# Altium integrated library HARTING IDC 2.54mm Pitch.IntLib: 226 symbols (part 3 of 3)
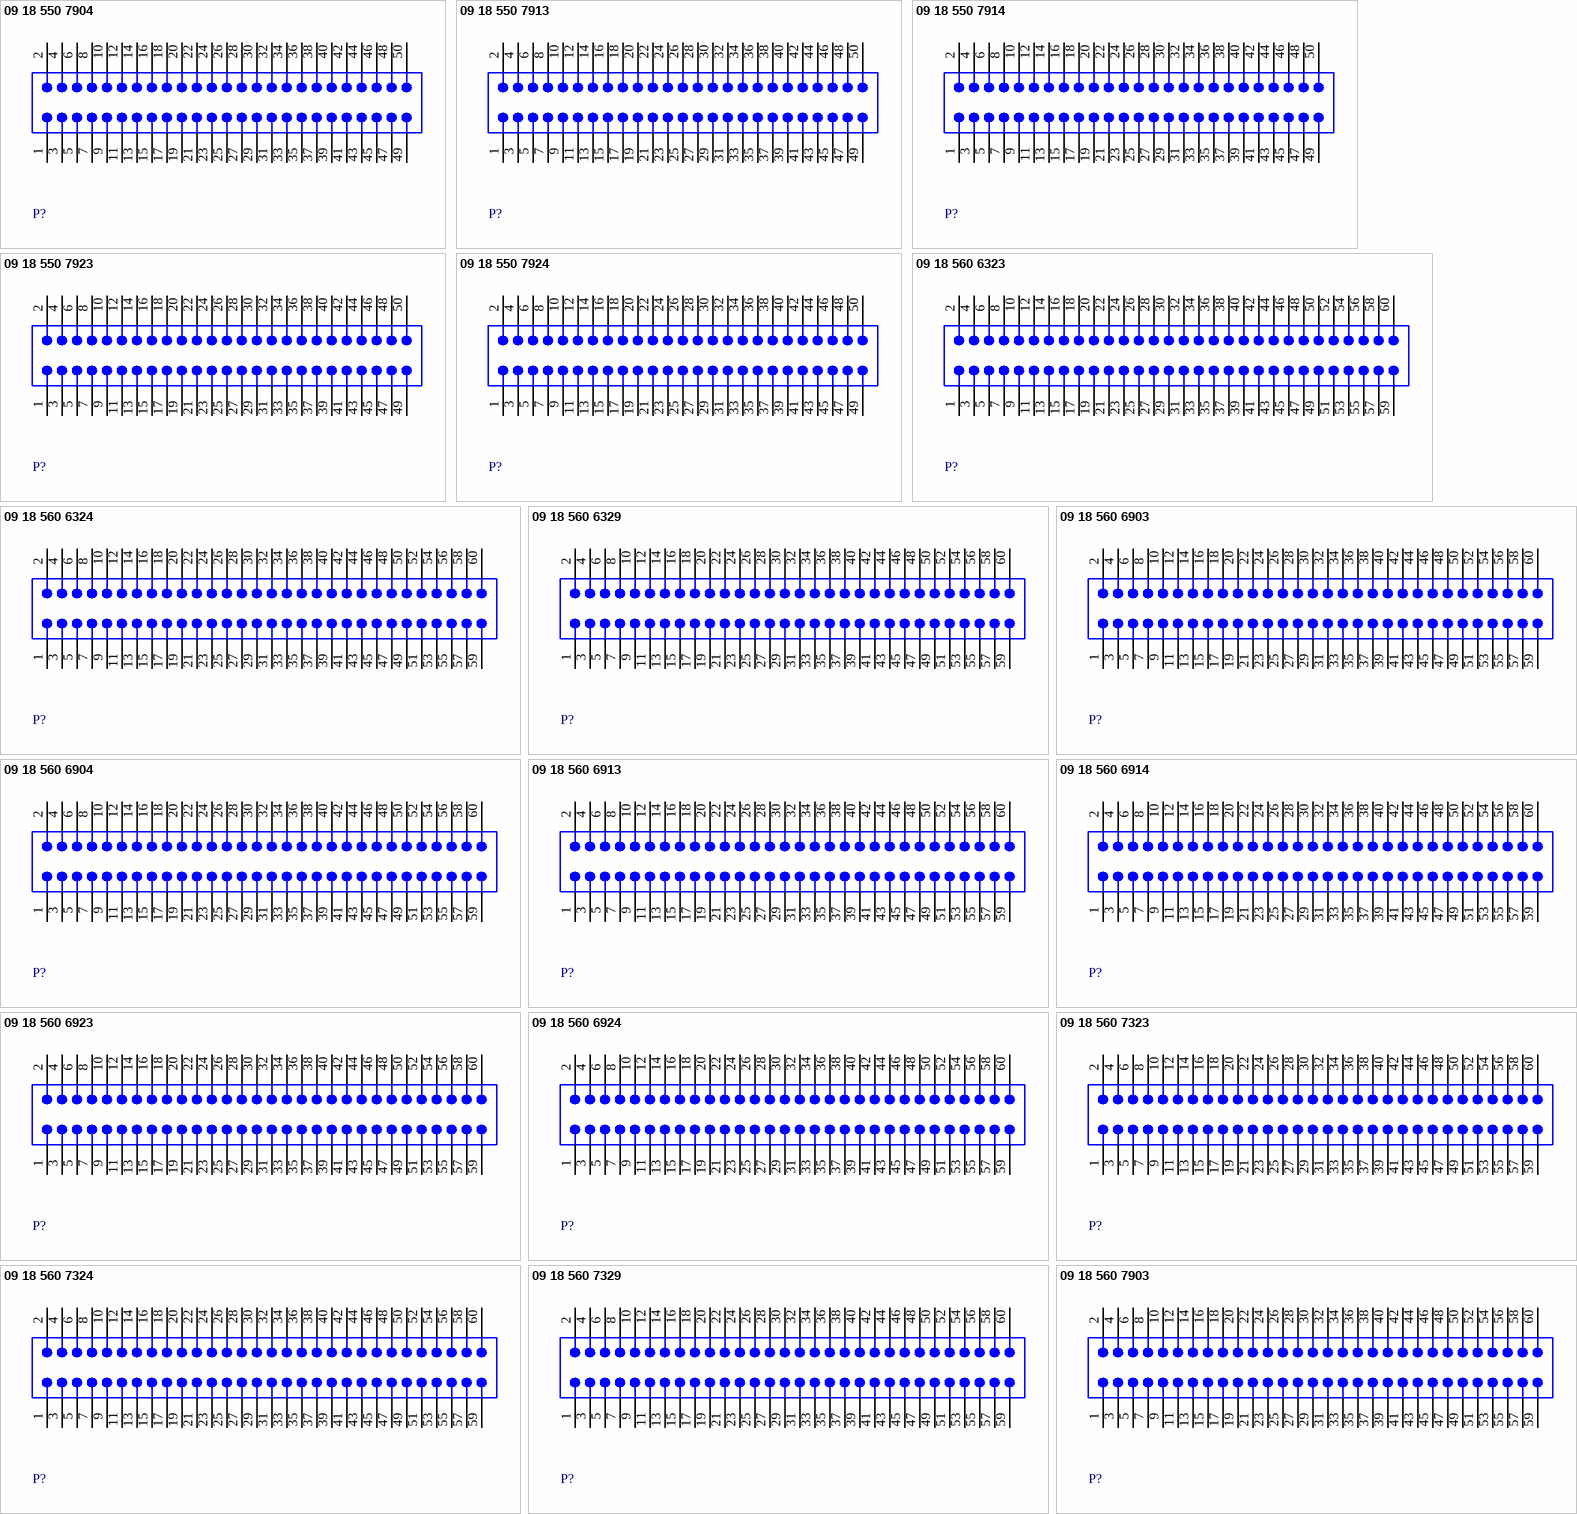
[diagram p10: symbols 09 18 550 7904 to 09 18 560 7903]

## 09 18 560 7324
designator P?
Flat Cable Connector (IDC), Low-Profile Male Header, Straight Solder Pin, 60 Contacts, Performance Level 3; PCB_Layout: Complies with manufacturer's recommendation.; DrillSize: Corresponds to nominal value.
footprint 918560x324 (Connector; IDC, Low Profile Male Header, Thru-Hole; 60 Position; Vertical; Pitch 2.54 mm; Body 84.02 x 9.2 x 9.45 mm (LxWxH))
pins: 1, 2, 3, 4, 5, 6, 7, 8, 9, 10, 11, 12, 13, 14, 15, 16, 17, 18, 19, 20, 21, 22, 23, 24, 25, 26, 27, 28, 29, 30, 31, 32, 33, 34, 35, 36, 37, 38, 39, 40, 41, 42, 43, 44, 45, 46, 47, 48, 49, 50, 51, 52, 53, 54, 55, 56, 57, 58, 59, 60

## 09 18 560 7329
designator P?
Flat Cable Connector (IDC), Standard Male Header, Straight Press-in Pin, 60 Contacts, Performance Level 3; PCB_Layout: Complies with manufacturer's recommendation.; DrillSize: Corresponds to nominal value.
footprint 918560x329 (Connector; IDC, Straight Press-in Pin, Thru-Hole; 60 Position; Vertical; Pitch 2.54 mm; Body 84.02 x 9.2 x 9.45 mm (LxWxH))
pins: 1, 2, 3, 4, 5, 6, 7, 8, 9, 10, 11, 12, 13, 14, 15, 16, 17, 18, 19, 20, 21, 22, 23, 24, 25, 26, 27, 28, 29, 30, 31, 32, 33, 34, 35, 36, 37, 38, 39, 40, 41, 42, 43, 44, 45, 46, 47, 48, 49, 50, 51, 52, 53, 54, 55, 56, 57, 58, 59, 60

## 09 18 560 7903
designator P?
Flat Cable Connector (IDC), Standard Male Header, Angled Solder Pin, 60 Contacts, Long Levers, Performance Level 3; PCB_Layout: Complies with manufacturer's recommendation.; DrillSize: Corresponds to nominal value.
footprint 918560x903 (Connector; IDC, Thru-Hole; 60 Position; Right Angle; Pitch 2.54 mm; Body 95.80 x 8.5 x 25.75 mm (LxHxW), Locking levers)
pins: 1, 2, 3, 4, 5, 6, 7, 8, 9, 10, 11, 12, 13, 14, 15, 16, 17, 18, 19, 20, 21, 22, 23, 24, 25, 26, 27, 28, 29, 30, 31, 32, 33, 34, 35, 36, 37, 38, 39, 40, 41, 42, 43, 44, 45, 46, 47, 48, 49, 50, 51, 52, 53, 54, 55, 56, 57, 58, 59, 60

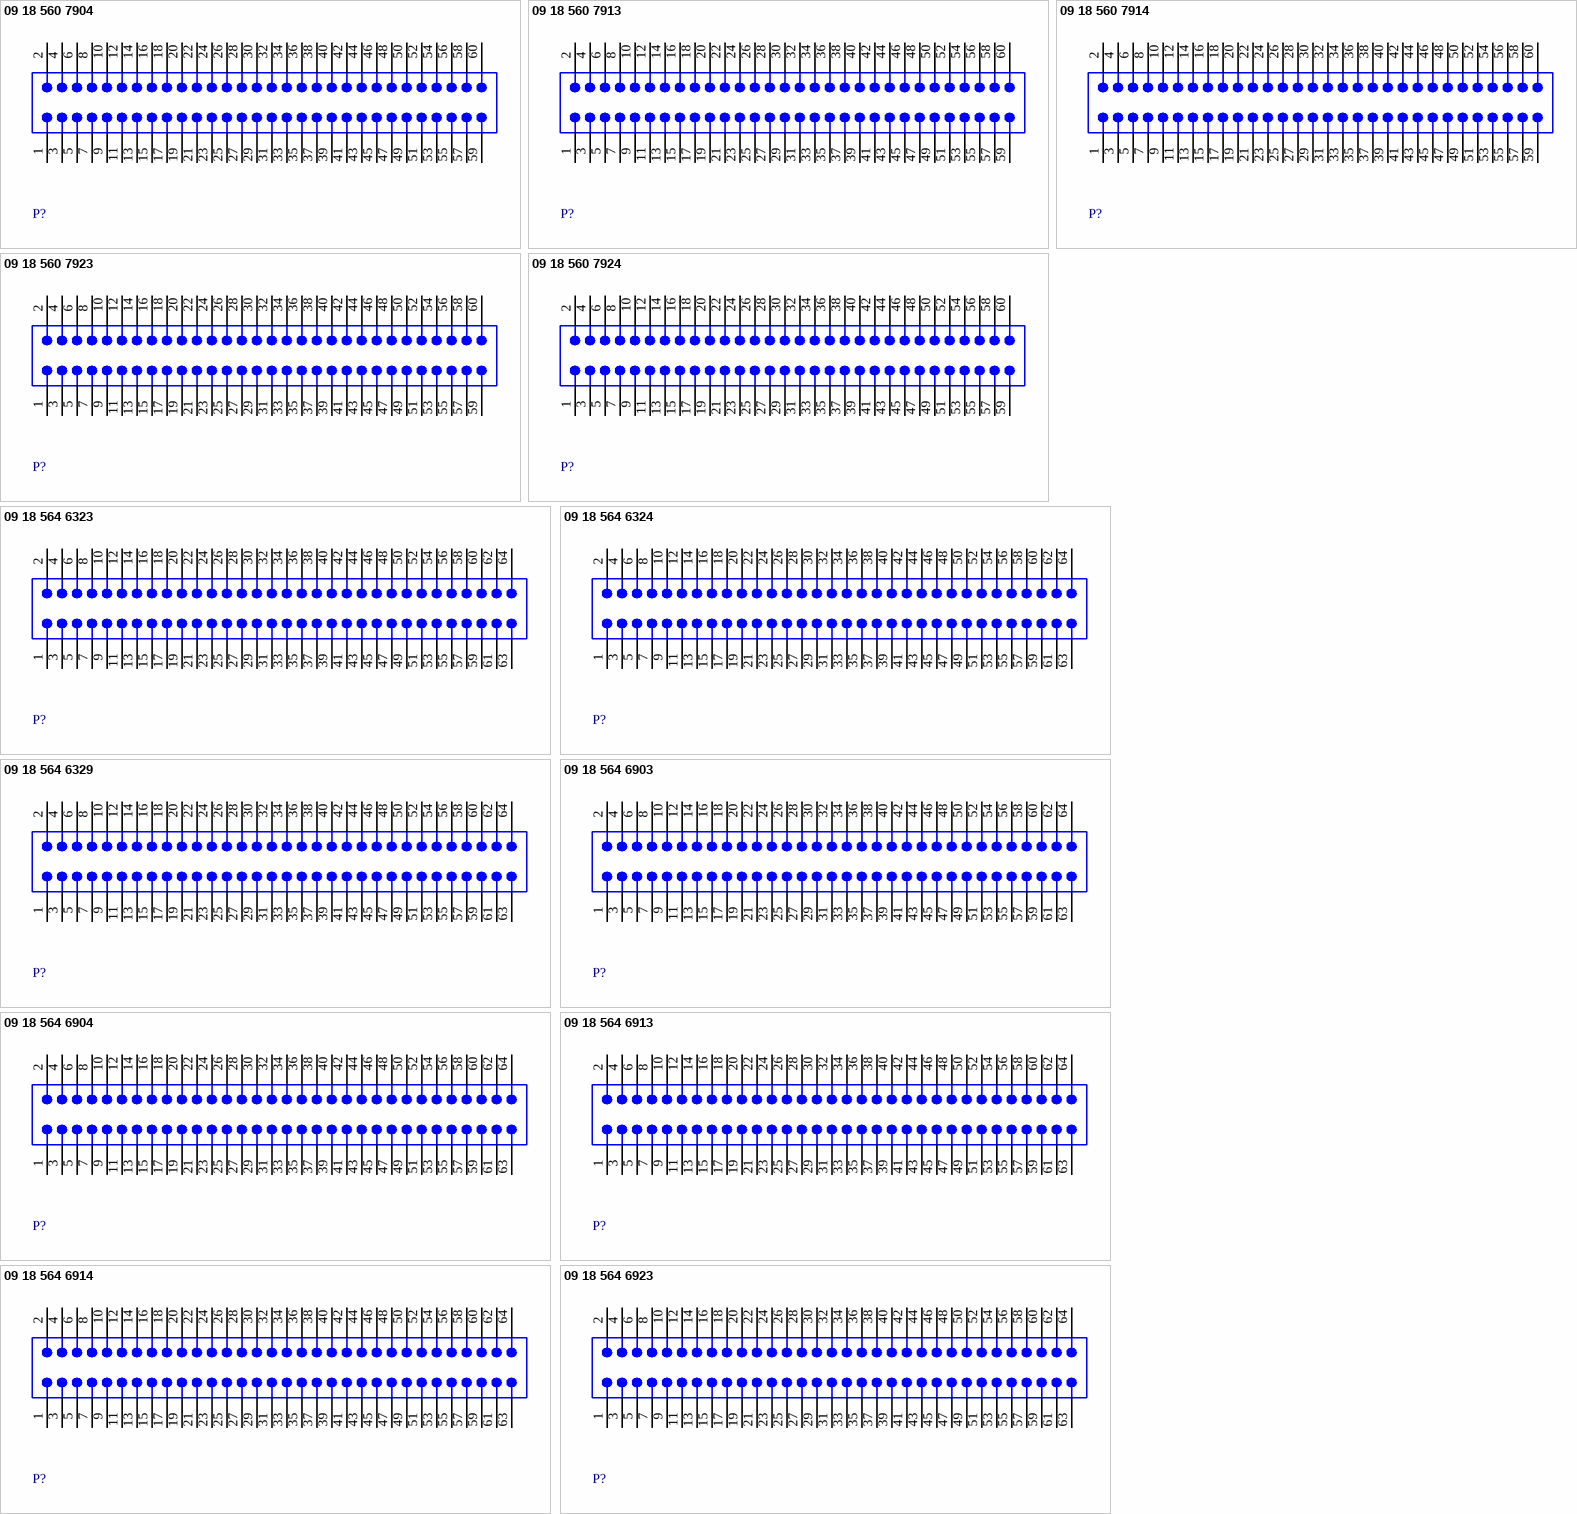
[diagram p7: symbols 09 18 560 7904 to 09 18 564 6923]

## 09 18 560 7904
designator P?
Flat Cable Connector (IDC), Standard Male Header, Straight Solder Pin, 60 Contacts, Long Levers, Performance Level 3; PCB_Layout: Complies with manufacturer's recommendation.; DrillSize: Corresponds to nominal value.
footprint 918560x904 (Connector; IDC, Thru-Hole; 60 Position; Vertical; Pitch 2.54 mm; Body 95.80 x 8.5 x 25.75 mm (LxWxH), Locking levers)
pins: 1, 2, 3, 4, 5, 6, 7, 8, 9, 10, 11, 12, 13, 14, 15, 16, 17, 18, 19, 20, 21, 22, 23, 24, 25, 26, 27, 28, 29, 30, 31, 32, 33, 34, 35, 36, 37, 38, 39, 40, 41, 42, 43, 44, 45, 46, 47, 48, 49, 50, 51, 52, 53, 54, 55, 56, 57, 58, 59, 60

## 09 18 560 7913
designator P?
Flat Cable Connector (IDC), Standard Male Header, Angled Solder Pin, 60 Contacts, Short Levers, Performance Level 3; PCB_Layout: Complies with manufacturer's recommendation.; DrillSize: Corresponds to nominal value.
footprint 918560x913 (Connector; IDC, Thru-Hole; 60 Position; Right Angle; Pitch 2.54 mm; Body 95.80 x 8.5 x 23.30 mm (LxHxW), Locking levers)
pins: 1, 2, 3, 4, 5, 6, 7, 8, 9, 10, 11, 12, 13, 14, 15, 16, 17, 18, 19, 20, 21, 22, 23, 24, 25, 26, 27, 28, 29, 30, 31, 32, 33, 34, 35, 36, 37, 38, 39, 40, 41, 42, 43, 44, 45, 46, 47, 48, 49, 50, 51, 52, 53, 54, 55, 56, 57, 58, 59, 60

## 09 18 560 7914
designator P?
Flat Cable Connector (IDC), Standard Male Header, Straight Solder Pin, 60 Contacts, Short Levers, Performance Level 3; PCB_Layout: Complies with manufacturer's recommendation.; DrillSize: Corresponds to nominal value.
footprint 918560x914 (Connector; IDC, Thru-Hole; 60 Position; Vertical; Pitch 2.54 mm; Body 95.80 x 8.5 x 23.30 mm (LxWxH), Locking levers)
pins: 1, 2, 3, 4, 5, 6, 7, 8, 9, 10, 11, 12, 13, 14, 15, 16, 17, 18, 19, 20, 21, 22, 23, 24, 25, 26, 27, 28, 29, 30, 31, 32, 33, 34, 35, 36, 37, 38, 39, 40, 41, 42, 43, 44, 45, 46, 47, 48, 49, 50, 51, 52, 53, 54, 55, 56, 57, 58, 59, 60

## 09 18 560 7923
designator P?
Flat Cable Connector (IDC), Standard Male Header, Angled Solder Pin, 60 Contacts, Without Levers, Performance Level 3; PCB_Layout: Complies with manufacturer's recommendation.; DrillSize: Corresponds to nominal value.
footprint 918560x923 (Connector; IDC, Thru-Hole; 60 Position; Right Angle; Pitch 2.54 mm; Body 95.80 x 8.5 x 17.30 mm (LxHxW), Without locking levers)
pins: 1, 2, 3, 4, 5, 6, 7, 8, 9, 10, 11, 12, 13, 14, 15, 16, 17, 18, 19, 20, 21, 22, 23, 24, 25, 26, 27, 28, 29, 30, 31, 32, 33, 34, 35, 36, 37, 38, 39, 40, 41, 42, 43, 44, 45, 46, 47, 48, 49, 50, 51, 52, 53, 54, 55, 56, 57, 58, 59, 60

## 09 18 560 7924
designator P?
Flat Cable Connector (IDC), Standard Male Header, Straight Solder Pin, 60 Contacts, Without Levers, Performance Level 3; PCB_Layout: Complies with manufacturer's recommendation.; DrillSize: Corresponds to nominal value.
footprint 918560x924 (Connector; IDC, Thru-Hole; 60 Position; Vertical; Pitch 2.54 mm; Body 95.80 x 8.5 x 17.30 mm (LxWxH), Without locking levers)
pins: 1, 2, 3, 4, 5, 6, 7, 8, 9, 10, 11, 12, 13, 14, 15, 16, 17, 18, 19, 20, 21, 22, 23, 24, 25, 26, 27, 28, 29, 30, 31, 32, 33, 34, 35, 36, 37, 38, 39, 40, 41, 42, 43, 44, 45, 46, 47, 48, 49, 50, 51, 52, 53, 54, 55, 56, 57, 58, 59, 60

## 09 18 564 6323
designator P?
Flat Cable Connector (IDC), Low-Profile Male Header, Angled Solder Pin, 64 Contacts, Performance Level 2; PCB_Layout: Complies with manufacturer's recommendation.; DrillSize: Corresponds to nominal value.
footprint 918564x323 (Connector; IDC, Low Profile Male Header, Thru-Hole; 64 Position; Right Angle; Pitch 2.54 mm; Body 89.10 x 8.9 x 9.2 mm (LxWxH))
pins: 1, 2, 3, 4, 5, 6, 7, 8, 9, 10, 11, 12, 13, 14, 15, 16, 17, 18, 19, 20, 21, 22, 23, 24, 25, 26, 27, 28, 29, 30, 31, 32, 33, 34, 35, 36, 37, 38, 39, 40, 41, 42, 43, 44, 45, 46, 47, 48, 49, 50, 51, 52, 53, 54, 55, 56, 57, 58, 59, 60, 61, 62, 63, 64

## 09 18 564 6324
designator P?
Flat Cable Connector (IDC), Low-Profile Male Header, Straight Solder Pin, 64 Contacts, Performance Level 2; PCB_Layout: Complies with manufacturer's recommendation.; DrillSize: Corresponds to nominal value.
footprint 918564x324 (Connector; IDC, Low Profile Male Header, Thru-Hole; 64 Position; Vertical; Pitch 2.54 mm; Body 89.10 x 9.2 x 9.45 mm (LxWxH))
pins: 1, 2, 3, 4, 5, 6, 7, 8, 9, 10, 11, 12, 13, 14, 15, 16, 17, 18, 19, 20, 21, 22, 23, 24, 25, 26, 27, 28, 29, 30, 31, 32, 33, 34, 35, 36, 37, 38, 39, 40, 41, 42, 43, 44, 45, 46, 47, 48, 49, 50, 51, 52, 53, 54, 55, 56, 57, 58, 59, 60, 61, 62, 63, 64

## 09 18 564 6329
designator P?
Flat Cable Connector (IDC), Standard Male Header, Straight Press-in Pin, 64 Contacts, Performance Level 2; PCB_Layout: Complies with manufacturer's recommendation.; DrillSize: Corresponds to nominal value.
footprint 918564x329 (Connector; IDC, Straight Press-in Pin, Thru-Hole; 64 Position; Vertical; Pitch 2.54 mm; Body 89.10 x 9.2 x 9.45 mm (LxWxH))
pins: 1, 2, 3, 4, 5, 6, 7, 8, 9, 10, 11, 12, 13, 14, 15, 16, 17, 18, 19, 20, 21, 22, 23, 24, 25, 26, 27, 28, 29, 30, 31, 32, 33, 34, 35, 36, 37, 38, 39, 40, 41, 42, 43, 44, 45, 46, 47, 48, 49, 50, 51, 52, 53, 54, 55, 56, 57, 58, 59, 60, 61, 62, 63, 64

## 09 18 564 6903
designator P?
Flat Cable Connector (IDC), Standard Male Header, Angled Solder Pin, 64 Contacts, Long Levers, Performance Level 2; PCB_Layout: Complies with manufacturer's recommendation.; DrillSize: Corresponds to nominal value.
footprint 918564x903 (Connector; IDC, Thru-Hole; 64 Position; Right Angle; Pitch 2.54 mm; Body 100.88 x 8.5 x 25.75 mm (LxHxW), Locking levers)
pins: 1, 2, 3, 4, 5, 6, 7, 8, 9, 10, 11, 12, 13, 14, 15, 16, 17, 18, 19, 20, 21, 22, 23, 24, 25, 26, 27, 28, 29, 30, 31, 32, 33, 34, 35, 36, 37, 38, 39, 40, 41, 42, 43, 44, 45, 46, 47, 48, 49, 50, 51, 52, 53, 54, 55, 56, 57, 58, 59, 60, 61, 62, 63, 64

## 09 18 564 6904
designator P?
Flat Cable Connector (IDC), Standard Male Header, Straight Solder Pin, 64 Contacts, Long Levers, Performance Level 2; PCB_Layout: Complies with manufacturer's recommendation.; DrillSize: Corresponds to nominal value.
footprint 918564x904 (Connector; IDC, Thru-Hole; 64 Position; Vertical; Pitch 2.54 mm; Body 100.88 x 8.5 x 25.75 mm (LxWxH), Locking levers)
pins: 1, 2, 3, 4, 5, 6, 7, 8, 9, 10, 11, 12, 13, 14, 15, 16, 17, 18, 19, 20, 21, 22, 23, 24, 25, 26, 27, 28, 29, 30, 31, 32, 33, 34, 35, 36, 37, 38, 39, 40, 41, 42, 43, 44, 45, 46, 47, 48, 49, 50, 51, 52, 53, 54, 55, 56, 57, 58, 59, 60, 61, 62, 63, 64

## 09 18 564 6913
designator P?
Flat Cable Connector (IDC), Standard Male Header, Angled Solder Pin, 64 Contacts, Short Levers, Performance Level 2; PCB_Layout: Complies with manufacturer's recommendation.; DrillSize: Corresponds to nominal value.
footprint 918564x913 (Connector; IDC, Thru-Hole; 64 Position; Right Angle; Pitch 2.54 mm; Body 100.88 x 8.5 x 23.30 mm (LxHxW), Locking levers)
pins: 1, 2, 3, 4, 5, 6, 7, 8, 9, 10, 11, 12, 13, 14, 15, 16, 17, 18, 19, 20, 21, 22, 23, 24, 25, 26, 27, 28, 29, 30, 31, 32, 33, 34, 35, 36, 37, 38, 39, 40, 41, 42, 43, 44, 45, 46, 47, 48, 49, 50, 51, 52, 53, 54, 55, 56, 57, 58, 59, 60, 61, 62, 63, 64

## 09 18 564 6914
designator P?
Flat Cable Connector (IDC), Standard Male Header, Straight Solder Pin, 64 Contacts, Short Levers, Performance Level 2; PCB_Layout: Complies with manufacturer's recommendation.; DrillSize: Corresponds to nominal value.
footprint 918564x914 (Connector; IDC, Thru-Hole; 64 Position; Vertical; Pitch 2.54 mm; Body 100.88 x 8.5 x 23.30 mm (LxWxH), Locking levers)
pins: 1, 2, 3, 4, 5, 6, 7, 8, 9, 10, 11, 12, 13, 14, 15, 16, 17, 18, 19, 20, 21, 22, 23, 24, 25, 26, 27, 28, 29, 30, 31, 32, 33, 34, 35, 36, 37, 38, 39, 40, 41, 42, 43, 44, 45, 46, 47, 48, 49, 50, 51, 52, 53, 54, 55, 56, 57, 58, 59, 60, 61, 62, 63, 64

## 09 18 564 6923
designator P?
Flat Cable Connector (IDC), Standard Male Header, Angled Solder Pin, 64 Contacts, Without Levers, Performance Level 2; PCB_Layout: Complies with manufacturer's recommendation.; DrillSize: Corresponds to nominal value.
footprint 918564x923 (Connector; IDC, Thru-Hole; 64 Position; Right Angle; Pitch 2.54 mm; Body 100.88 x 8.5 x 17.30 mm (LxHxW), Without locking levers)
pins: 1, 2, 3, 4, 5, 6, 7, 8, 9, 10, 11, 12, 13, 14, 15, 16, 17, 18, 19, 20, 21, 22, 23, 24, 25, 26, 27, 28, 29, 30, 31, 32, 33, 34, 35, 36, 37, 38, 39, 40, 41, 42, 43, 44, 45, 46, 47, 48, 49, 50, 51, 52, 53, 54, 55, 56, 57, 58, 59, 60, 61, 62, 63, 64

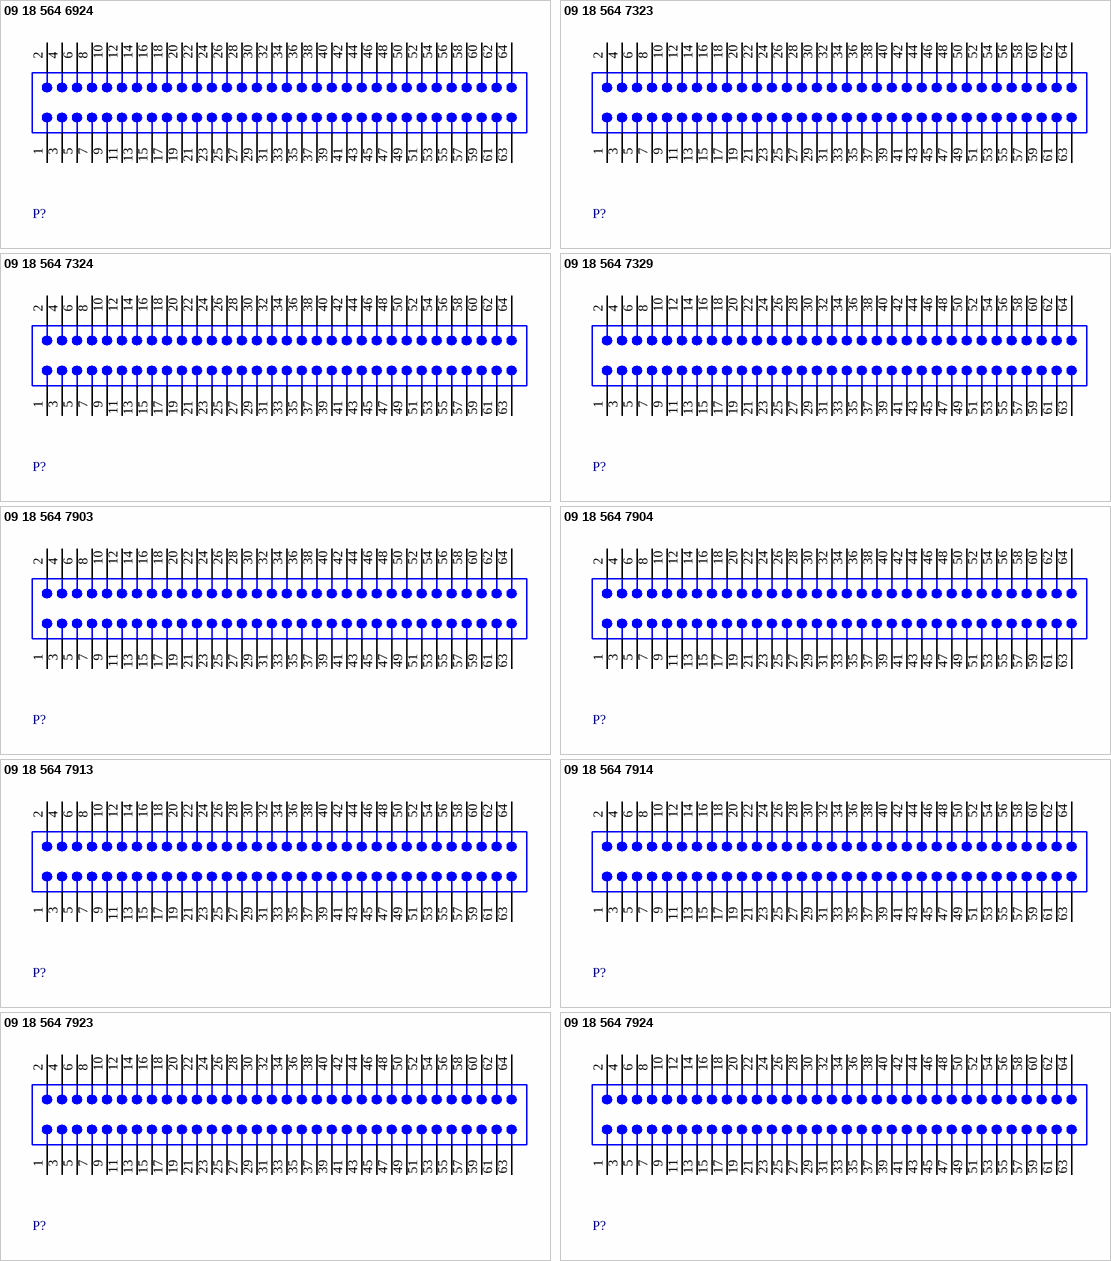
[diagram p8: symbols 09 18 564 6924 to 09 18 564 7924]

## 09 18 564 6924
designator P?
Flat Cable Connector (IDC), Standard Male Header, Straight Solder Pin, 64 Contacts, Without Levers, Performance Level 2; PCB_Layout: Complies with manufacturer's recommendation.; DrillSize: Corresponds to nominal value.
footprint 918564x924 (Connector; IDC, Thru-Hole; 64 Position; Vertical; Pitch 2.54 mm; Body 100.88 x 8.5 x 17.30 mm (LxWxH), Without locking levers)
pins: 1, 2, 3, 4, 5, 6, 7, 8, 9, 10, 11, 12, 13, 14, 15, 16, 17, 18, 19, 20, 21, 22, 23, 24, 25, 26, 27, 28, 29, 30, 31, 32, 33, 34, 35, 36, 37, 38, 39, 40, 41, 42, 43, 44, 45, 46, 47, 48, 49, 50, 51, 52, 53, 54, 55, 56, 57, 58, 59, 60, 61, 62, 63, 64

## 09 18 564 7323
designator P?
Flat Cable Connector (IDC), Low-Profile Male Header, Angled Solder Pin, 64 Contacts, Performance Level 3; PCB_Layout: Complies with manufacturer's recommendation.; DrillSize: Corresponds to nominal value.
footprint 918564x323 (Connector; IDC, Low Profile Male Header, Thru-Hole; 64 Position; Right Angle; Pitch 2.54 mm; Body 89.10 x 8.9 x 9.2 mm (LxWxH))
pins: 1, 2, 3, 4, 5, 6, 7, 8, 9, 10, 11, 12, 13, 14, 15, 16, 17, 18, 19, 20, 21, 22, 23, 24, 25, 26, 27, 28, 29, 30, 31, 32, 33, 34, 35, 36, 37, 38, 39, 40, 41, 42, 43, 44, 45, 46, 47, 48, 49, 50, 51, 52, 53, 54, 55, 56, 57, 58, 59, 60, 61, 62, 63, 64

## 09 18 564 7324
designator P?
Flat Cable Connector (IDC), Low-Profile Male Header, Straight Solder Pin, 64 Contacts, Performance Level 3; PCB_Layout: Complies with manufacturer's recommendation.; DrillSize: Corresponds to nominal value.
footprint 918564x324 (Connector; IDC, Low Profile Male Header, Thru-Hole; 64 Position; Vertical; Pitch 2.54 mm; Body 89.10 x 9.2 x 9.45 mm (LxWxH))
pins: 1, 2, 3, 4, 5, 6, 7, 8, 9, 10, 11, 12, 13, 14, 15, 16, 17, 18, 19, 20, 21, 22, 23, 24, 25, 26, 27, 28, 29, 30, 31, 32, 33, 34, 35, 36, 37, 38, 39, 40, 41, 42, 43, 44, 45, 46, 47, 48, 49, 50, 51, 52, 53, 54, 55, 56, 57, 58, 59, 60, 61, 62, 63, 64

## 09 18 564 7329
designator P?
Flat Cable Connector (IDC), Standard Male Header, Straight Press-in Pin, 64 Contacts, Performance Level 3; PCB_Layout: Complies with manufacturer's recommendation.; DrillSize: Corresponds to nominal value.
footprint 918564x329 (Connector; IDC, Straight Press-in Pin, Thru-Hole; 64 Position; Vertical; Pitch 2.54 mm; Body 89.10 x 9.2 x 9.45 mm (LxWxH))
pins: 1, 2, 3, 4, 5, 6, 7, 8, 9, 10, 11, 12, 13, 14, 15, 16, 17, 18, 19, 20, 21, 22, 23, 24, 25, 26, 27, 28, 29, 30, 31, 32, 33, 34, 35, 36, 37, 38, 39, 40, 41, 42, 43, 44, 45, 46, 47, 48, 49, 50, 51, 52, 53, 54, 55, 56, 57, 58, 59, 60, 61, 62, 63, 64

## 09 18 564 7903
designator P?
Flat Cable Connector (IDC), Standard Male Header, Angled Solder Pin, 64 Contacts, Long Levers, Performance Level 3; PCB_Layout: Complies with manufacturer's recommendation.; DrillSize: Corresponds to nominal value.
footprint 918564x903 (Connector; IDC, Thru-Hole; 64 Position; Right Angle; Pitch 2.54 mm; Body 100.88 x 8.5 x 25.75 mm (LxHxW), Locking levers)
pins: 1, 2, 3, 4, 5, 6, 7, 8, 9, 10, 11, 12, 13, 14, 15, 16, 17, 18, 19, 20, 21, 22, 23, 24, 25, 26, 27, 28, 29, 30, 31, 32, 33, 34, 35, 36, 37, 38, 39, 40, 41, 42, 43, 44, 45, 46, 47, 48, 49, 50, 51, 52, 53, 54, 55, 56, 57, 58, 59, 60, 61, 62, 63, 64

## 09 18 564 7904
designator P?
Flat Cable Connector (IDC), Standard Male Header, Straight Solder Pin, 64 Contacts, Long Levers, Performance Level 3; PCB_Layout: Complies with manufacturer's recommendation.; DrillSize: Corresponds to nominal value.
footprint 918564x904 (Connector; IDC, Thru-Hole; 64 Position; Vertical; Pitch 2.54 mm; Body 100.88 x 8.5 x 25.75 mm (LxWxH), Locking levers)
pins: 1, 2, 3, 4, 5, 6, 7, 8, 9, 10, 11, 12, 13, 14, 15, 16, 17, 18, 19, 20, 21, 22, 23, 24, 25, 26, 27, 28, 29, 30, 31, 32, 33, 34, 35, 36, 37, 38, 39, 40, 41, 42, 43, 44, 45, 46, 47, 48, 49, 50, 51, 52, 53, 54, 55, 56, 57, 58, 59, 60, 61, 62, 63, 64

## 09 18 564 7913
designator P?
Flat Cable Connector (IDC), Standard Male Header, Angled Solder Pin, 64 Contacts, Short Levers, Performance Level 3; PCB_Layout: Complies with manufacturer's recommendation.; DrillSize: Corresponds to nominal value.
footprint 918564x913 (Connector; IDC, Thru-Hole; 64 Position; Right Angle; Pitch 2.54 mm; Body 100.88 x 8.5 x 23.30 mm (LxHxW), Locking levers)
pins: 1, 2, 3, 4, 5, 6, 7, 8, 9, 10, 11, 12, 13, 14, 15, 16, 17, 18, 19, 20, 21, 22, 23, 24, 25, 26, 27, 28, 29, 30, 31, 32, 33, 34, 35, 36, 37, 38, 39, 40, 41, 42, 43, 44, 45, 46, 47, 48, 49, 50, 51, 52, 53, 54, 55, 56, 57, 58, 59, 60, 61, 62, 63, 64

## 09 18 564 7914
designator P?
Flat Cable Connector (IDC), Standard Male Header, Straight Solder Pin, 64 Contacts, Short Levers, Performance Level 3; PCB_Layout: Complies with manufacturer's recommendation.; DrillSize: Corresponds to nominal value.
footprint 918564x914 (Connector; IDC, Thru-Hole; 64 Position; Vertical; Pitch 2.54 mm; Body 100.88 x 8.5 x 23.30 mm (LxWxH), Locking levers)
pins: 1, 2, 3, 4, 5, 6, 7, 8, 9, 10, 11, 12, 13, 14, 15, 16, 17, 18, 19, 20, 21, 22, 23, 24, 25, 26, 27, 28, 29, 30, 31, 32, 33, 34, 35, 36, 37, 38, 39, 40, 41, 42, 43, 44, 45, 46, 47, 48, 49, 50, 51, 52, 53, 54, 55, 56, 57, 58, 59, 60, 61, 62, 63, 64

## 09 18 564 7923
designator P?
Flat Cable Connector (IDC), Standard Male Header, Angled Solder Pin, 64 Contacts, Without Levers, Performance Level 3; PCB_Layout: Complies with manufacturer's recommendation.; DrillSize: Corresponds to nominal value.
footprint 918564x923 (Connector; IDC, Thru-Hole; 64 Position; Right Angle; Pitch 2.54 mm; Body 100.88 x 8.5 x 17.30 mm (LxHxW), Without locking levers)
pins: 1, 2, 3, 4, 5, 6, 7, 8, 9, 10, 11, 12, 13, 14, 15, 16, 17, 18, 19, 20, 21, 22, 23, 24, 25, 26, 27, 28, 29, 30, 31, 32, 33, 34, 35, 36, 37, 38, 39, 40, 41, 42, 43, 44, 45, 46, 47, 48, 49, 50, 51, 52, 53, 54, 55, 56, 57, 58, 59, 60, 61, 62, 63, 64

## 09 18 564 7924
designator P?
Flat Cable Connector (IDC), Standard Male Header, Straight Solder Pin, 64 Contacts, Without Levers, Performance Level 3; PCB_Layout: Complies with manufacturer's recommendation.; DrillSize: Corresponds to nominal value.
footprint 918564x924 (Connector; IDC, Thru-Hole; 64 Position; Vertical; Pitch 2.54 mm; Body 100.88 x 8.5 x 17.30 mm (LxWxH), Without locking levers)
pins: 1, 2, 3, 4, 5, 6, 7, 8, 9, 10, 11, 12, 13, 14, 15, 16, 17, 18, 19, 20, 21, 22, 23, 24, 25, 26, 27, 28, 29, 30, 31, 32, 33, 34, 35, 36, 37, 38, 39, 40, 41, 42, 43, 44, 45, 46, 47, 48, 49, 50, 51, 52, 53, 54, 55, 56, 57, 58, 59, 60, 61, 62, 63, 64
